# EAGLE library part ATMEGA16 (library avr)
MICROCONTROLLER 16 Kbytes FLASH 1 kbytes SRAM 512 bytes EEPROM USART 8-channel 10 bit ADC
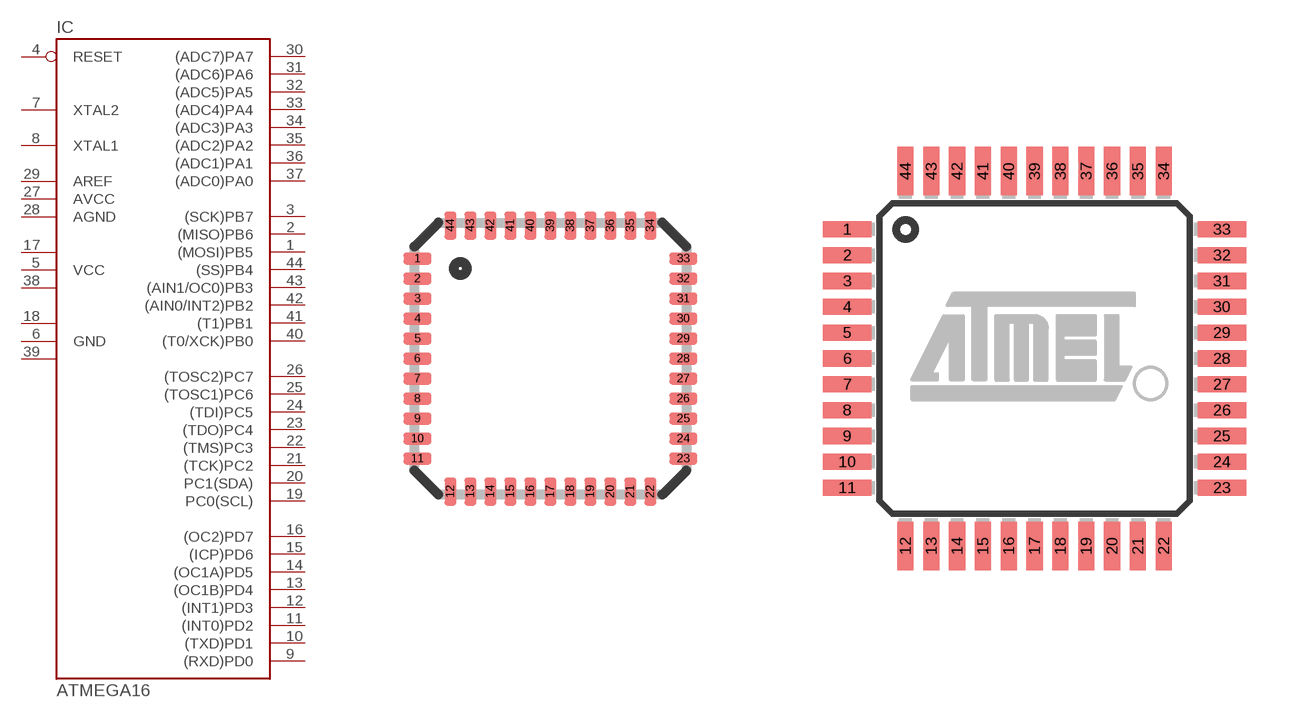
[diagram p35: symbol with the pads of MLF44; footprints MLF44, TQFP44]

Designator prefix IC

## ATMEGA16-16M, ATMEGA16L-8M  [MLF44]
1  (MOSI)PB5
2  (MISO)PB6
3  (SCK)PB7
4  RESET  in
5  VCC  pwr
6  GND  pwr
7  XTAL2
8  XTAL1
9  (RXD)PD0
10  (TXD)PD1
11  (INT0)PD2
12  (INT1)PD3
13  (OC1B)PD4
14  (OC1A)PD5
15  (ICP)PD6
16  (OC2)PD7
17  VCC1  pwr
18  GND1  pwr
19  PC0(SCL)
20  PC1(SDA)
21  (TCK)PC2
22  (TMS)PC3
23  (TDO)PC4
24  (TDI)PC5
25  (TOSC1)PC6
26  (TOSC2)PC7
27  AVCC  pwr
28  AGND  pwr
29  AREF  pwr
30  (ADC7)PA7
31  (ADC6)PA6
32  (ADC5)PA5
33  (ADC4)PA4
34  (ADC3)PA3
35  (ADC2)PA2
36  (ADC1)PA1
37  (ADC0)PA0
38  VCC2  pwr
39  GND2  pwr
40  (T0/XCK)PB0
41  (T1)PB1
42  (AIN0/INT2)PB2
43  (AIN1/OC0)PB3
44  (SS)PB4

## ATMEGA16-16A, ATMEGA16L-8A  [TQFP44]
Pads as for MLF44

## Footprint MLF44 (pad centres in mm)
44M1 Micro Lead Frame package (MLF)
smd 0.7 x 0.3: 1 -3.325,2.5; 2 -3.325,2; 3 -3.325,1.5; 4 -3.325,1; 5 -3.325,0.5; 6 -3.325,0; 7 -3.325,-0.5; 8 -3.325,-1; 9 -3.325,-1.5; 10 -3.325,-2; 11 -3.325,-2.5; 23 3.325,-2.5; 24 3.325,-2; 25 3.325,-1.5; 26 3.325,-1; 27 3.325,-0.5; 28 3.325,0; 29 3.325,0.5; 30 3.325,1; 31 3.325,1.5; 32 3.325,2; 33 3.325,2.5
smd 0.3 x 0.7: 12 -2.5,-3.325; 13 -2,-3.325; 14 -1.5,-3.325; 15 -1,-3.325; 16 -0.5,-3.325; 17 0,-3.325; 18 0.5,-3.325; 19 1,-3.325; 20 1.5,-3.325; 21 2,-3.325; 22 2.5,-3.325; 34 2.5,3.325; 35 2,3.325; 36 1.5,3.325; 37 1,3.325; 38 0.5,3.325; 39 0,3.325; 40 -0.5,3.325; 41 -1,3.325; 42 -1.5,3.325; 43 -2,3.325; 44 -2.5,3.325

## Footprint TQFP44 (pad centres in mm)
Thin Plasic Quad Flat Package
smd 1.5 x 0.5: 1 -5.8,4; 2 -5.8,3.2; 3 -5.8,2.4; 4 -5.8,1.6; 5 -5.8,0.8; 6 -5.8,0; 7 -5.8,-0.8; 8 -5.8,-1.6; 9 -5.8,-2.4; 10 -5.8,-3.2; 11 -5.8,-4; 23 5.8,-4; 24 5.8,-3.2; 25 5.8,-2.4; 26 5.8,-1.6; 27 5.8,-0.8; 28 5.8,0; 29 5.8,0.8; 30 5.8,1.6; 31 5.8,2.4; 32 5.8,3.2; 33 5.8,4
smd 0.5 x 1.5: 12 -4,-5.8; 13 -3.2,-5.8; 14 -2.4,-5.8; 15 -1.6,-5.8; 16 -0.8,-5.8; 17 0,-5.8; 18 0.8,-5.8; 19 1.6,-5.8; 20 2.4,-5.8; 21 3.2,-5.8; 22 4,-5.8; 34 4,5.8; 35 3.2,5.8; 36 2.4,5.8; 37 1.6,5.8; 38 0.8,5.8; 39 0,5.8; 40 -0.8,5.8; 41 -1.6,5.8; 42 -2.4,5.8; 43 -3.2,5.8; 44 -4,5.8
